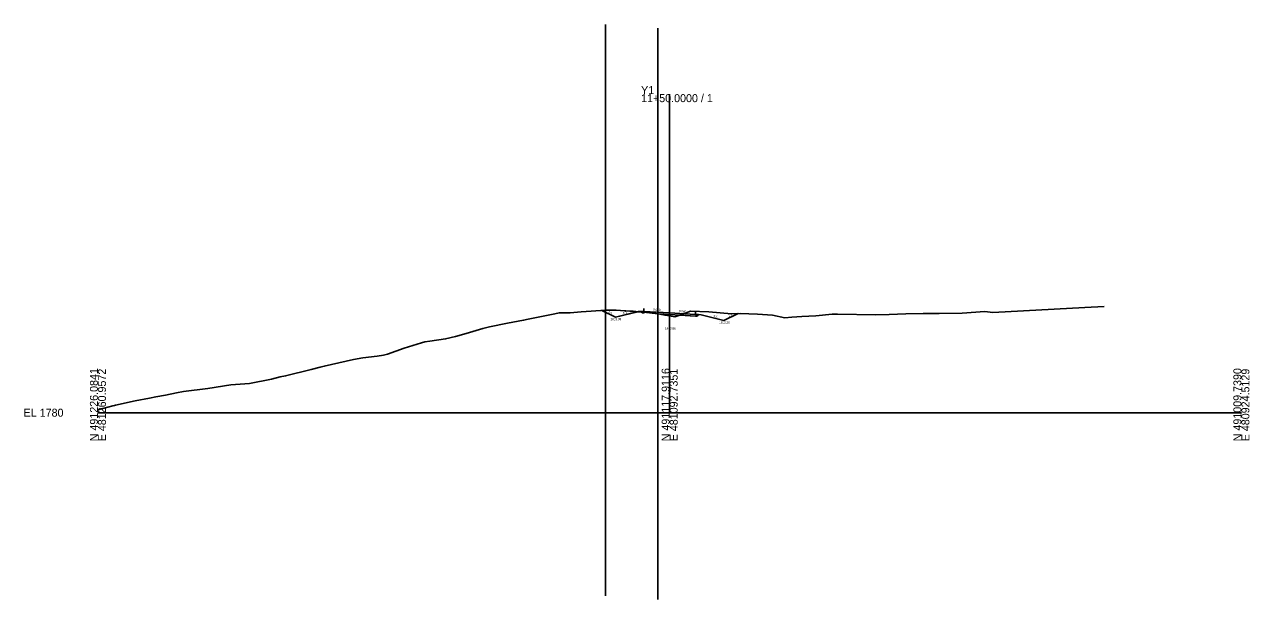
# Model space of a CAD drawing. Extents: x -26 to 403, y -10 to 6561.
# Drawn here: x -25.7 to 402.8, y 1434.6 to 1635.9 of the extents above; entities that cross this region are included whole.
import ezdxf

# ---------------------------------------------------------------- set-up
doc = ezdxf.new("R2010")
doc.units = 0
for name, color, linetype in [('Exist Cross Section Cell', 7, 'Continuous'), ('Exist XS Center Line Elevation Label', 7, 'Continuous'), ('Exist XS Ground Line', 7, 'Continuous'), ('Prop Road Sect_ Boring - Header (ID Tx)', 7, 'Continuous'), ('Prop Road Sect_ Material - Tx (Composite Desc)', 7, 'Continuous'), ('Prop XS Ditch Slope Text', 7, 'Continuous'), ('Prop XS Ditch Standard Text', 7, 'Continuous'), ('Prop XS EOT Tick Mark', 7, 'Continuous'), ('Prop XS Finish Grade', 7, 'Continuous'), ('Prop XS Finish Grade Earthwork', 7, 'Continuous'), ('Prop XS Finish Grade Pavement', 7, 'Continuous'), ('Prop XS Pvmt Edge Slope', 7, 'Continuous'), ('Prop XS SE Text', 7, 'Continuous'), ('Prop XS Side Slope Text', 7, 'Continuous'), ('Prop XS Subgrade Earthwork', 7, 'Continuous'), ('Scratch_Level_1', 7, 'Continuous'), ('Scratch_Level_4', 7, 'Continuous')]:
    doc.layers.add(name, color=color, linetype=linetype)

msp = doc.modelspace()

# ---------------------------------------------------------------- linework, layer by layer
at = {"layer": 'Exist Cross Section Cell'}
for p, q in [((200, 1500), (200, 1611.48)), ((0, 1500), (200, 1500)), ((200, 1500), (400, 1500))]:
    msp.add_line(p, q, dxfattribs=at)
at = {"layer": 'Exist XS Ground Line'}
msp.add_lwpolyline([(0, 1501.01), (5.2, 1502.35), (5.79, 1502.5), (6.17, 1502.61), (13.03, 1504.11), (18.06, 1505.1), (20.27, 1505.56), (23.69, 1506.18), (27.5, 1506.96), (29.96, 1507.43), (38.4, 1508.45), (46.54, 1509.75), (53.02, 1510.23), (60.67, 1511.78), (63.69, 1512.55), (65.63, 1512.89), (74.56, 1515.15), (77.78, 1515.96), (79.17, 1516.26), (89.41, 1518.59), (92.64, 1519.2), (97.66, 1519.83), (99.88, 1520.12), (101.3, 1520.5), (107.11, 1522.55), (113.2, 1524.43), (114.35, 1524.85), (116.15, 1525.04), (121.59, 1525.81), (125.09, 1526.67), (128.83, 1527.69), (134.64, 1529.47), (136.06, 1529.87), (136.98, 1530.08), (143.3, 1531.38), (148.87, 1532.37), (150.54, 1532.78), (159.24, 1534.5), (160.91, 1534.89), (161.38, 1534.9), (165.19, 1534.97), (169.09, 1535.27), (177.68, 1535.87), (178.5, 1535.92), (180.55, 1535.86), (181.24, 1535.84), (182.82, 1535.77), (184.21, 1535.7), (184.65, 1535.68), (186.03, 1535.56), (186.33, 1535.53), (187.18, 1535.52), (188.22, 1535.42), (189.83, 1535.27), (190.14, 1535.24), (190.66, 1535.2), (193.11, 1535), (193.65, 1534.96), (194.52, 1534.86), (195.91, 1534.55), (198.4, 1534.12), (200, 1533.86), (201.83, 1533.55), (203.19, 1533.97), (207.31, 1535.53), (213.74, 1535.28), (221.67, 1534.65), (224.69, 1534.75), (230.69, 1534.44), (235.94, 1534.18), (240.31, 1533.18), (242.78, 1533.41), (246.26, 1533.62), (251.09, 1533.86), (256.86, 1534.49), (257.9, 1534.49), (258.73, 1534.49), (272.15, 1534.26), (276.82, 1534.42), (282.58, 1534.61), (288.64, 1534.75), (294.22, 1534.74), (302.38, 1534.88), (310.31, 1535.37), (313.05, 1535.11), (345.25, 1536.86), (352.05, 1537.16)], dxfattribs=at)
at = {"layer": 'Prop Road Sect_ Boring - Header (ID Tx)'}
for points in [[(190.46, 1534.92), (189.96, 1535.42), (191, 1535.46)], [(209.58, 1533.81), (210.09, 1534.32), (209, 1534.38)]]:
    msp.add_lwpolyline(points, close=True, dxfattribs=at)
at = {"layer": 'Prop Road Sect_ Material - Tx (Composite Desc)'}
for points in [[(181, 1533.38), (176.23, 1535.77), (177.68, 1535.87), (178.5, 1535.92), (180.55, 1535.86), (181.24, 1535.84), (182.82, 1535.77), (184.21, 1535.7), (184.65, 1535.68), (186.03, 1535.56), (186.33, 1535.53), (187.18, 1535.52), (188.22, 1535.42), (188.89, 1535.36)], [(188.89, 1535.36), (189.83, 1535.27), (190.14, 1535.24), (189.96, 1535.42), (189, 1535.38)], [(190.46, 1534.92), (190.14, 1535.24), (190.66, 1535.2), (191, 1535.17), (191, 1534.92)], [(200, 1534.38), (195.83, 1534.63), (195.83, 1534.57), (195.91, 1534.55), (198.4, 1534.12), (200, 1533.86), (201.83, 1533.55), (203.19, 1533.97), (203.7, 1534.16)], [(203.7, 1534.16), (207.31, 1535.53), (213.74, 1535.28), (221.67, 1534.65), (223.92, 1534.72), (219, 1532.26), (211, 1534.26), (210.09, 1534.32), (209.58, 1533.81), (209, 1533.84)]]:
    msp.add_lwpolyline(points, close=True, dxfattribs=at)
at = {"layer": 'Prop XS EOT Tick Mark'}
for p, q in [((191, 1535.46), (191, 1536.46)), ((209, 1534.38), (209, 1535.38))]:
    msp.add_line(p, q, dxfattribs=at)
at = {"layer": 'Prop XS Finish Grade'}
for p, q in [((191, 1535.46), (189.96, 1535.42)), ((209, 1534.38), (210.09, 1534.32))]:
    msp.add_line(p, q, dxfattribs=at)
at = {"layer": 'Prop XS Finish Grade Earthwork'}
for p, q in [((181, 1533.38), (176.23, 1535.77)), ((189, 1535.38), (181, 1533.38)), ((189.96, 1535.42), (189, 1535.38)), ((210.09, 1534.32), (211, 1534.26)), ((211, 1534.26), (219, 1532.26)), ((219, 1532.26), (223.92, 1534.72))]:
    msp.add_line(p, q, dxfattribs=at)
at = {"layer": 'Prop XS Finish Grade Pavement'}
for p, q in [((191, 1535.46), (200, 1534.92)), ((200, 1534.92), (209, 1534.38))]:
    msp.add_line(p, q, dxfattribs=at)
at = {"layer": 'Prop XS Pvmt Edge Slope'}
for p, q in [((191, 1535.46), (190.46, 1534.92)), ((209, 1534.38), (209.58, 1533.81))]:
    msp.add_line(p, q, dxfattribs=at)
at = {"layer": 'Prop XS Subgrade Earthwork'}
for p, q in [((190.46, 1534.92), (189.96, 1535.42)), ((191, 1534.92), (190.46, 1534.92)), ((191, 1535.17), (191, 1534.92)), ((200, 1534.38), (195.83, 1534.63)), ((195.83, 1534.63), (195.83, 1534.57)), ((209, 1533.84), (200, 1534.38)), ((209.58, 1533.81), (210.09, 1534.32)), ((209, 1533.84), (209.58, 1533.81))]:
    msp.add_line(p, q, dxfattribs=at)
at = {"layer": 'Scratch_Level_1'}
for p, q in [((177.57, 1635.86), (177.57, 1435.86)), ((195.83, 1634.63), (195.83, 1434.63))]:
    msp.add_line(p, q, dxfattribs=at)
at = {"layer": 'Scratch_Level_4'}
msp.add_line((195.83, 1534.57), (191, 1535.17), dxfattribs=at)

# ---------------------------------------------------------------- texts
at = {"layer": 'Exist Cross Section Cell'}
for s, p in [('Y1', (190, 1611.48)), ('11+50.0000 / 1', (190, 1608.68)), ('EL 1780', (-26, 1498.6))]:
    msp.add_text(s, height=2.8, dxfattribs=at).set_placement(p)
for s, p in [('N 491226.0841', (0, 1490)), ('E 481260.9572', (2.8, 1490)), ('N 491117.9116', (200, 1490)), ('E 481092.7351', (202.8, 1490)), ('N 491009.7390', (400, 1490)), ('E 480924.5129', (402.8, 1490))]:
    msp.add_text(s, height=2.8, rotation=90, dxfattribs=at).set_placement(p)
at = {"layer": 'Exist XS Center Line Elevation Label'}
msp.add_text('1813.86', height=0.75, dxfattribs=at).set_placement((198.38, 1529.11))
at = {"layer": 'Prop XS Ditch Slope Text'}
for rotation, p in [(14.0362, (183.71, 1534.49)), (345.9638, (215.29, 1533.61))]:
    msp.add_text('4:1', height=0.75, rotation=rotation, dxfattribs=at).set_placement(p)
at = {"layer": 'Prop XS Ditch Standard Text'}
for s, p in [('1813.38', (179.31, 1532.38)), ('1812.26', (217.31, 1531.19))]:
    msp.add_text(s, height=0.75, dxfattribs=at).set_placement(p)
at = {"layer": 'Prop XS SE Text'}
for p in [(194.19, 1535.77), (203.19, 1535.23)]:
    msp.add_text('0.060', height=0.75, rotation=356.5664, dxfattribs=at).set_placement(p)
at = {"layer": 'Prop XS Side Slope Text'}
for rotation, p in [(333.4349, (178.43, 1534.98)), (26.5651, (220.7, 1533.48))]:
    msp.add_text('2:1', height=0.75, rotation=rotation, dxfattribs=at).set_placement(p)

doc.saveas('drawing.dxf')
